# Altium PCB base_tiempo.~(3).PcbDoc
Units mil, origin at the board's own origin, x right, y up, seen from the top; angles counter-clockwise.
Board outline 6000 x 4000 mil, 2 copper layers (Top Layer, Bottom Layer); 15 components, 22 nets, 88 pads, 0 vias.
Unrouted connection lines stored in the file: 51.
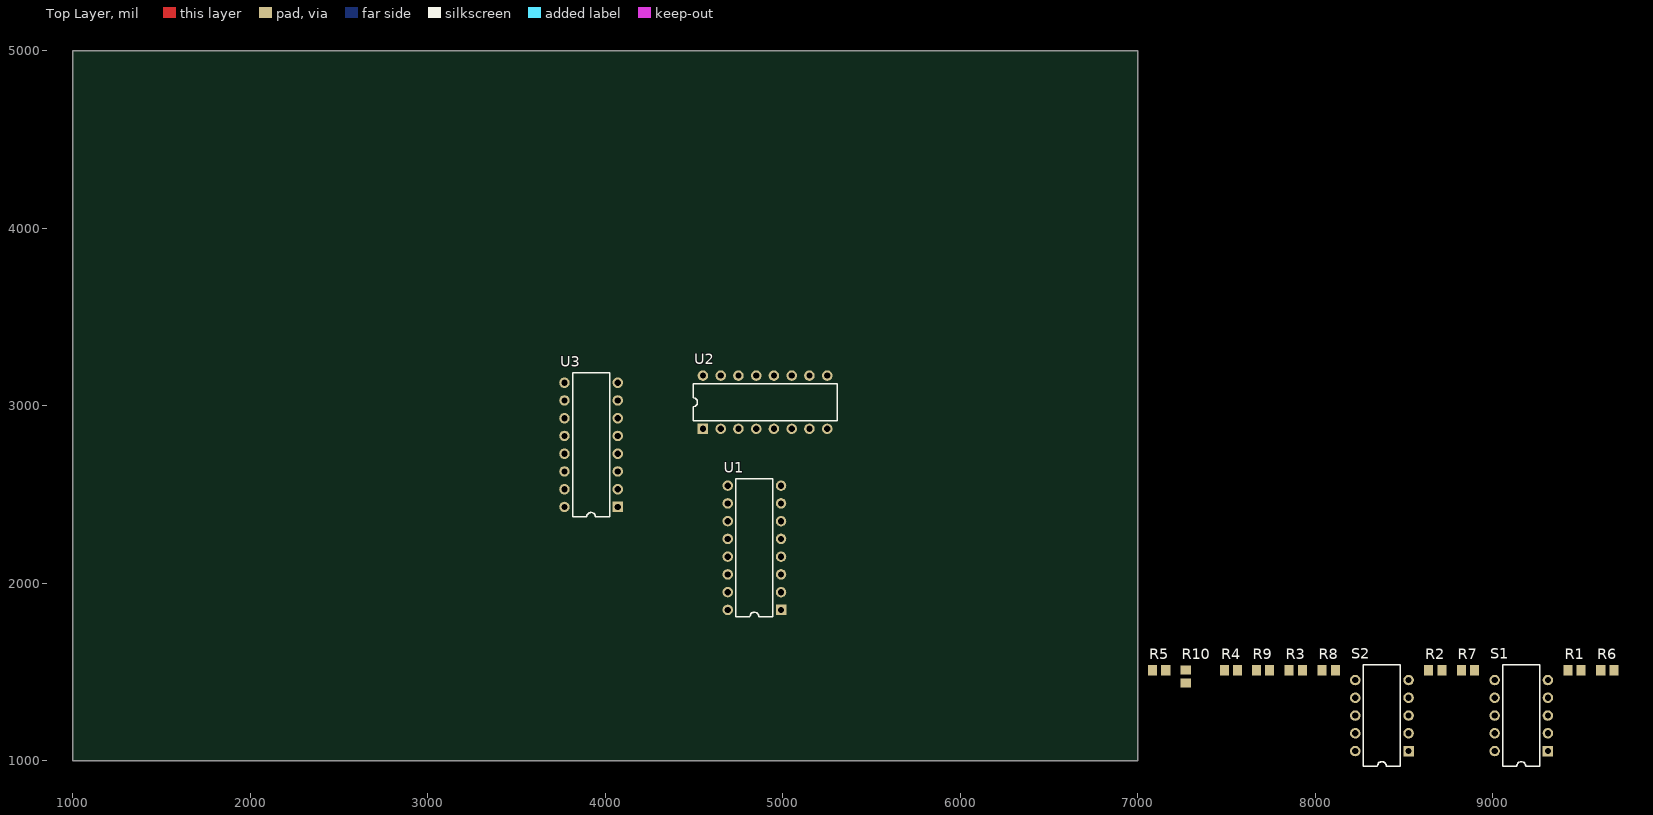
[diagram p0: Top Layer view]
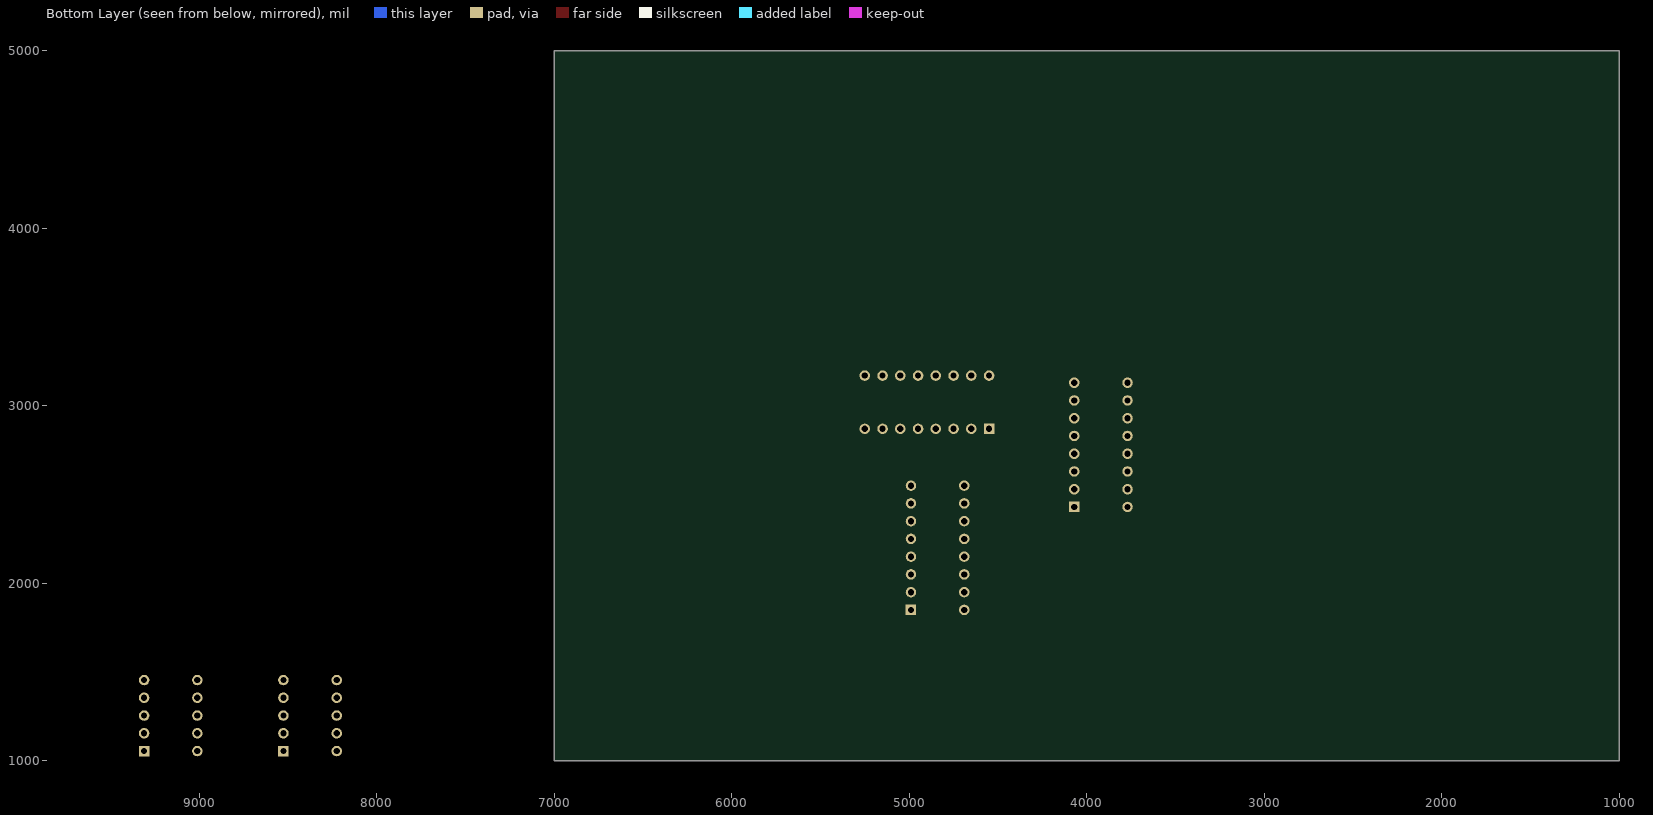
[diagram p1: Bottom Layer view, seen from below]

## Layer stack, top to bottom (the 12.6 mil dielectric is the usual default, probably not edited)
Top Layer: signal copper 1.4
Dielectric: dielectric 12.6, FR-4, Dk 4.8
Bottom Layer: signal copper 1.4

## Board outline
1000,1000 7000,1000 7000,5000 1000,5000

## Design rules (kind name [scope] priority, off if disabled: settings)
Clearance [All] p1: gap=10
PolygonConnect [All] p1: connectstyle=Relief reliefconductorwidth=10 reliefentries=4 polygonreliefangle="90 Angle"
RoomDefinition Selector [InComponentClass('Selector')] p1: confinementstyle=ConfineIn formatcopy=TRUE lockcomponents=FALSE outline 7045,960 9720,960 9720,1650 7045,1650
RoomDefinition Buffer_5Bits [InComponentClass('Buffer_5Bits')] p2: confinementstyle=ConfineIn formatcopy=TRUE lockcomponents=FALSE outline 0,0 2000,0 2000,1000 0,1000
RoomDefinition base_tiempo [InComponentClass('base_tiempo')] p3: confinementstyle=ConfineIn formatcopy=TRUE lockcomponents=FALSE outline 7045,960 7845,960 7845,1860 7045,1860
RoutingVias [All] p1: holewidth=28 width=50 viastyle="Through Hole" minholewidth=28 minwidth=50 maxholewidth=28 maxwidth=50
SilkscreenOverComponentPads [All] p1: minsilkscreentomaskgap=10
SolderMaskExpansion [All] p1: expansion=4
TestPointUsage [All] p1: valid=0 allowmultiple=FALSE
Testpoint [All] p1: side=15 testpointundercomponent=TRUE minsize=40 maxsize=100 preferedsize=60 minholesize=0 maxholesize=40 preferedholesize=32 testpointgrid=1 style=1023 order=0123456789
Width [All] p1: maxlimit=10 minlimit=10 preferedwidth=10
23 further rules are at their usual default settings.

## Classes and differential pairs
component class Selector: R1 R2 R3 R4 R5 R6 R7 R8 R9 R10 S1 S2
component class Buffer_5Bits: U2 U3
component class base_tiempo: U1

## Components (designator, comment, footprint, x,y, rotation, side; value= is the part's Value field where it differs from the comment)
R1 "Res Semi" 2012[0805] 9460,1510 r0 top
R2 "Res Semi" 2012[0805] 8675,1510 r0 top
R3 "Res Semi" 2012[0805] 7890,1510 r0 top
R4 "Res Semi" 2012[0805] 7525,1510 r0 top
R5 "Res Semi" 2012[0805] 7120,1510 r0 top
R6 "Res Semi" 2012[0805] 9645,1510 r0 top
R7 "Res Semi" 2012[0805] 8860,1510 r0 top
R8 "Res Semi" 2012[0805] 8075,1510 r0 top
R9 "Res Semi" 2012[0805] 7705,1510 r0 top
R10 "Res Semi" 2012[0805] 7270,1475 r90 top
S1 "SW DIP-5" N10A 9160,1255 r90 top
S2 "SW DIP-5" N10A 8375,1255 r90 top
U1 "SN74HC4040N" N016 4840,2200 r90 top
U2 "M54HC4050F1R" DIP16 4900,3020 r0 top
U3 "M54HC4049F1R" DIP16 3920,2780 r90 top

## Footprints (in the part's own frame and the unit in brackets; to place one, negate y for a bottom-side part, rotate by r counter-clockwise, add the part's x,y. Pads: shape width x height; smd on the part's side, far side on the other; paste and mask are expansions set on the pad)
2012[0805] [mm] "Chip Resistor; Body 2.0 x 1.3 mm (LxW typ)"
  rect 1.3x1.5 smd: 1(-0.95,0) 2(0.95,0)
DIP16 [mm] "DIP; 16 Leads; Row Spacing 7.62 mm; Pitch 2.54 mm"
  rect 1.5x1.5 hole 0.9: 1(-8.89,-3.81)
  round 1.5 hole 0.9: 2(-6.35,-3.81) 3(-3.81,-3.81) 4(-1.27,-3.81) 5(1.27,-3.81) 6(3.81,-3.81) 7(6.35,-3.81) 8(8.89,-3.81) 9(8.89,3.81) 10(6.35,3.81) 11(3.81,3.81) 12(1.27,3.81) 13(-1.27,3.81) 14(-3.81,3.81) 15(-6.35,3.81) 16(-8.89,3.81)
  silkscreen extent -10.3,-2.65 10.3,2.65
N10A [mm] "DIP; 10 Leads; Row Spacing 7.62 mm; Pitch 2.54 mm"
  rect 1.5x1.5 hole 0.9: 1(-5.08,-3.81)
  round 1.5 hole 0.9: 2(-2.54,-3.81) 3(0,-3.81) 4(2.54,-3.81) 5(5.08,-3.81) 6(5.08,3.81) 7(2.54,3.81) 8(0,3.81) 9(-2.54,3.81) 10(-5.08,3.81)
  silkscreen extent -7.25,-2.65 7.25,2.65
N016 [mm] "DIP; 16 Leads; Row Spacing 7.62 mm; Pitch 2.54 mm"
  rect 1.5x1.5 hole 0.9: 1(-8.89,-3.81)
  round 1.5 hole 0.9: 2(-6.35,-3.81) 3(-3.81,-3.81) 4(-1.27,-3.81) 5(1.27,-3.81) 6(3.81,-3.81) 7(6.35,-3.81) 8(8.89,-3.81) 9(8.89,3.81) 10(6.35,3.81) 11(3.81,3.81) 12(1.27,3.81) 13(-1.27,3.81) 14(-3.81,3.81) 15(-6.35,3.81) 16(-8.89,3.81)
  silkscreen extent -9.85,-2.65 9.85,2.65

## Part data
R1 R2 R3 R4 R5 R6 R7 R8 R9 R10: "Semiconductor Resistor"
S1 S2: "DIP Switch, 5 Position, SPST"
U1: "12-Bit Asynchronous Binary Counter"
U2: "Hex Buffer/Converter Non-Inverting"
U3: "Hex Buffer/Converter Invertering"

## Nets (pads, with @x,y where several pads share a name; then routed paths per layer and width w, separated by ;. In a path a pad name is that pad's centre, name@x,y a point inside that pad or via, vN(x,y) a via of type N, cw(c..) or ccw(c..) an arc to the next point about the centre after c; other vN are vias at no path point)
/SEL_B_0: R1.2 S2.1 U3.2
/SEL_B_1: R2.2 S2.2 U3.4
/SEL_B_2: R3.2 S2.3 U3.6
/SEL_B_3: R4.2 S2.4 U3.10
/SEL_B_4: R5.2 S2.5 U3.12
B_0: U1.9 U2.3 U3.3
B_1: U1.7 U2.5 U3.5
B_2: U1.6 U2.7 U3.7
B_3: U1.5 U2.9 U3.9
B_4: U1.3 U2.11 U3.11
GND: R1.1 R2.1 R3.1 R4.1 R5.1 R6.1 R7.1 R8.1 R9.1 R10.1 U1.8 U2.8 U3.8
O_0: S1.10 S2.10
O_1: S1.9 S2.9
O_2: S1.8 S2.8
O_3: S1.7 S2.7
O_4: S1.6 S2.6
SEL_B_0: R6.2 S1.1 U2.2
SEL_B_1: R7.2 S1.2 U2.4
SEL_B_2: R8.2 S1.3 U2.6
SEL_B_3: R9.2 S1.4 U2.10
SEL_B_4: R10.2 S1.5 U2.12
VCC: U1.10 U1.11 U1.16 U2.1 U3.1
pads on no net: U1.1 U1.2 U1.4 U1.12 U1.13 U1.14 U1.15 U2.13 U2.14 U2.15 U2.16 U3.13 U3.14 U3.15 U3.16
